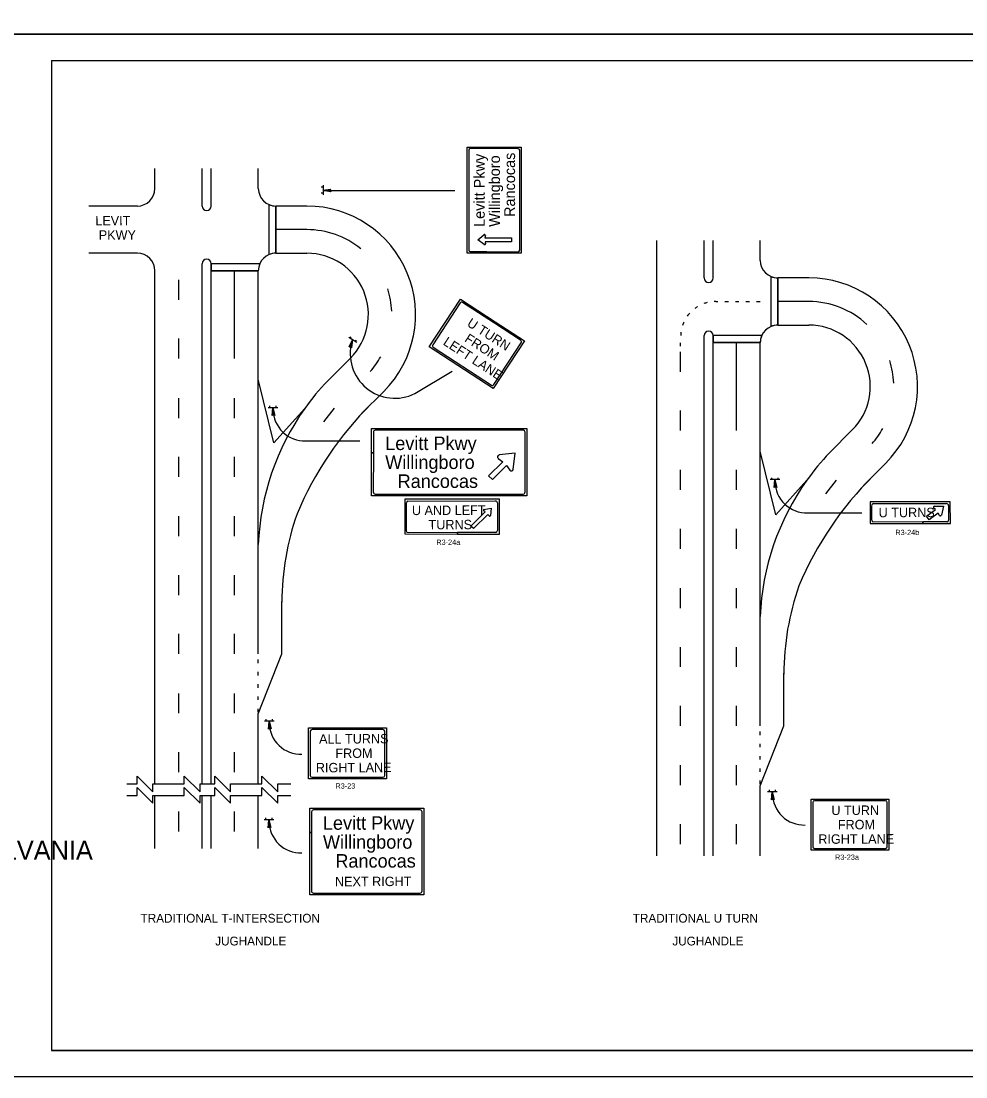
# Model space of a CAD drawing. Extents: x 644898 to 648326, y 298294 to 300670.
# Drawn here: x 647444 to 647982, y 298888 to 299490 of the extents above; entities that cross this region are included whole.
import ezdxf

# ---------------------------------------------------------------- set-up
doc = ezdxf.new("R2010")
doc.units = 0
for name, color, linetype in [('1', 7, 'Continuous'), ('2', 7, 'Continuous'), ('XCS-GRID-MIN', 7, 'Continuous')]:
    doc.layers.add(name, color=color, linetype=linetype)

msp = doc.modelspace()

# ---------------------------------------------------------------- linework, layer by layer
at = {"layer": '1'}
for p, q in [((647461.32, 299467.49), (648247.32, 299467.49)), ((647461.32, 299467.49), (647461.32, 298903.49)), ((648247.32, 298903.49), (647461.32, 298903.49)), ((647461.32, 298903.49), (648047.32, 298903.49))]:
    msp.add_line(p, q, dxfattribs=at)
at = {"layer": '2'}
for p, q in [((647698.12, 299357.77), (647698.12, 299418.14)), ((647698.12, 299418.14), (647728.92, 299418.14)), ((647699, 299416.54), (647699, 299359.53)), ((647727.12, 299417.32), (647699.78, 299417.34)), ((647728.04, 299359.53), (647728.04, 299416.49)), ((647728.92, 299418.14), (647728.92, 299357.77)), ((647520.31, 299394.64), (647520.31, 299406.06)), ((647547.19, 299384.64), (647547.19, 299406.06)), ((647552.28, 299384.64), (647552.28, 299406.06)), ((647579.16, 299394.64), (647579.16, 299406.06)), ((647616, 299395.44), (647614.87, 299395.44)), ((647616, 299391.94), (647614.87, 299391.94)), ((647616, 299396.44), (647616, 299390.94)), ((647616, 299393.57), (647691.11, 299393.57)), ((647510.31, 299384.64), (647482.57, 299384.64)), ((647585.16, 299385.48), (647585.16, 299356.94)), ((647589.16, 299384.65), (647589.16, 299357.77)), ((647606.83, 299384.64), (647589.16, 299384.64)), ((647606.83, 299371.2), (647589.16, 299371.2)), ((647704.1, 299365.4), (647707.54, 299368.27)), ((647708.46, 299367.81), (647708.25, 299366.6)), ((647708.25, 299366.6), (647723.35, 299366.6)), ((647723.35, 299366.6), (647723.35, 299364.34)), ((647707.76, 299362.66), (647704.1, 299365.4)), ((647723.35, 299364.34), (647708.34, 299364.34)), ((647708.34, 299364.34), (647708.53, 299363.19)), ((647806.19, 299014.4), (647806.19, 299365.09)), ((647833.06, 299343.67), (647833.06, 299365.09)), ((647838.15, 299343.67), (647838.15, 299365.09)), ((647865.03, 299353.67), (647865.03, 299365.09)), ((647510.31, 299357.77), (647482.57, 299357.77)), ((647589.16, 299357.77), (647606.83, 299357.77)), ((647709.21, 299357.82), (647698.12, 299357.77)), ((647709.21, 299358.65), (647709.21, 299357.82)), ((647709.21, 299357.82), (647709.21, 299358.65)), ((647728.92, 299357.77), (647709.21, 299357.82)), ((647547.19, 299174.37), (647547.19, 299351.77)), ((647552.28, 299174.37), (647552.28, 299351.77)), ((647579.99, 299351.77), (647552.28, 299351.77)), ((647520.31, 299174.37), (647520.31, 299347.77)), ((647533.81, 299331.24), (647533.81, 299342.62)), ((647579.16, 299347.77), (647552.28, 299347.77)), ((647565.66, 299297.74), (647565.66, 299347.77)), ((647579.16, 299285.94), (647579.16, 299347.77)), ((647871.03, 299344.51), (647871.03, 299315.97)), ((647875.03, 299343.68), (647875.03, 299316.8)), ((647892.7, 299343.67), (647875.03, 299343.67)), ((647676.55, 299304.43), (647694.31, 299331.65)), ((647694.31, 299331.65), (647714.13, 299318.72)), ((647694.05, 299329.43), (647678.48, 299305.56)), ((647713.59, 299317.89), (647695.44, 299329.72)), ((647839.69, 299330.24), (647840.83, 299330.24)), ((647844.82, 299330.24), (647846.84, 299330.24)), ((647850.83, 299330.24), (647852.87, 299330.24)), ((647856.84, 299330.24), (647858.88, 299330.24)), ((647862.85, 299330.24), (647864.89, 299330.24)), ((647892.7, 299330.24), (647875.03, 299330.24)), ((647713.59, 299317.89), (647714.13, 299318.72)), ((647714.13, 299318.72), (647713.59, 299317.89)), ((647714.13, 299318.72), (647730.76, 299307.88)), ((647728.54, 299308.14), (647713.59, 299317.89)), ((647875.03, 299316.8), (647892.7, 299316.8)), ((647533.81, 299297.74), (647533.81, 299309.12)), ((647635.24, 299306.8), (647630.63, 299309.81)), ((647631.47, 299309.26), (647632.09, 299310.21)), ((647634.4, 299307.35), (647635.02, 299308.29)), ((647730.76, 299307.88), (647713, 299280.66)), ((647713.26, 299282.88), (647728.83, 299306.75)), ((647819.69, 299304.8), (647819.69, 299306.78)), ((647833.06, 299014.4), (647833.06, 299310.8)), ((647838.15, 299014.4), (647838.15, 299310.8)), ((647865.86, 299310.8), (647838.15, 299310.8)), ((647865.03, 299306.8), (647838.15, 299306.8)), ((647851.53, 299256.77), (647851.53, 299306.8)), ((647865.03, 299244.97), (647865.03, 299306.8)), ((647713, 299280.66), (647676.55, 299304.43)), ((647678.77, 299304.18), (647711.88, 299282.59)), ((647819.69, 299290.27), (647819.69, 299301.65)), ((647618.5, 299284.95), (647631.58, 299298.02)), ((647668.35, 299277.79), (647689.58, 299290.51)), ((647579.16, 299174.37), (647579.16, 299285.94)), ((647637.97, 299266.42), (647650.57, 299279.03)), ((647533.81, 299263.87), (647533.81, 299275.24)), ((647565.66, 299263.87), (647565.66, 299275.24)), ((647585.8, 299269.71), (647585.8, 299270.84)), ((647589.3, 299269.71), (647589.3, 299270.84)), ((647590.3, 299269.71), (647584.8, 299269.71)), ((647616.48, 299261.61), (647622.59, 299269.47)), ((647819.69, 299256.77), (647819.69, 299268.15)), ((647643.58, 299244.11), (647643.58, 299257.98)), ((647643.58, 299257.98), (647732.13, 299257.98)), ((647730.13, 299256.88), (647645.78, 299256.88)), ((647731.1, 299221.72), (647731.12, 299255.9)), ((647732.13, 299257.98), (647732.13, 299219.47)), ((647904.38, 299243.98), (647917.45, 299257.06)), ((647606.18, 299250.84), (647637.05, 299250.84)), ((647533.81, 299230.37), (647533.81, 299241.74)), ((647565.66, 299230.37), (647565.66, 299241.74)), ((647644.68, 299244.11), (647643.58, 299244.11)), ((647643.58, 299219.47), (647643.58, 299244.11)), ((647643.58, 299244.11), (647644.68, 299244.11)), ((647715.8, 299240.74), (647718.41, 299238.96)), ((647725.43, 299243.91), (647716.35, 299242.81)), ((647724.33, 299234.56), (647725.43, 299243.91)), ((647865.03, 299133.4), (647865.03, 299244.97)), ((647718.41, 299238.96), (647710.3, 299230.98)), ((647712.5, 299228.78), (647720.48, 299236.76)), ((647720.48, 299236.76), (647722.4, 299234.14)), ((647819.69, 299222.9), (647819.69, 299234.27)), ((647851.53, 299222.9), (647851.53, 299234.27)), ((647923.84, 299225.45), (647936.45, 299238.06)), ((647710.3, 299230.98), (647712.5, 299228.78)), ((647876.18, 299228.75), (647870.68, 299228.75)), ((647871.68, 299228.75), (647871.68, 299229.87)), ((647875.18, 299228.75), (647875.18, 299229.87)), ((647902.35, 299220.64), (647908.47, 299228.5)), ((647732.13, 299219.47), (647643.58, 299219.47)), ((647645.78, 299220.57), (647730.07, 299220.57)), ((647716.43, 299217.58), (647662.52, 299217.58)), ((647662.52, 299217.58), (647662.58, 299197.81)), ((647664.39, 299216.54), (647714.07, 299216.61)), ((647716.43, 299197.74), (647716.43, 299217.58)), ((647663.49, 299199.62), (647663.46, 299215.53)), ((647700.2, 299202.29), (647708.38, 299210.38)), ((647708.38, 299210.38), (647707.52, 299210.99)), ((647707.68, 299211.83), (647711.79, 299212.43)), ((647711.79, 299212.43), (647711.43, 299208.37)), ((647715.32, 299215.58), (647715.32, 299199.76)), ((647973.17, 299216.14), (647927.59, 299216.14)), ((647927.59, 299216.14), (647927.65, 299203.75)), ((647928.56, 299205.63), (647928.53, 299214.09)), ((647929.46, 299215.1), (647970.95, 299215.18)), ((647959.71, 299207.94), (647964.76, 299211.66)), ((647964.76, 299211.66), (647963.8, 299212.57)), ((647964.15, 299213.57), (647969.34, 299213.57)), ((647969.34, 299213.57), (647968.16, 299208.61)), ((647972.21, 299214.1), (647972.18, 299205.79)), ((647973.31, 299203.75), (647973.17, 299216.14)), ((647533.81, 299196.49), (647533.81, 299207.87)), ((647565.66, 299196.49), (647565.66, 299207.87)), ((647709.9, 299208.99), (647701.65, 299200.83)), ((647710.54, 299208.07), (647709.9, 299208.99)), ((647892.05, 299209.87), (647922.92, 299209.87)), ((647957.61, 299204.69), (647929.54, 299204.6)), ((647971.63, 299204.76), (647957.61, 299204.69)), ((647957.63, 299203.8), (647957.61, 299204.69)), ((647957.61, 299204.69), (647957.63, 299203.8)), ((647961.22, 299205.88), (647959.71, 299207.94)), ((647966.38, 299209.66), (647961.22, 299205.88)), ((647967.01, 299208.41), (647966.38, 299209.66)), ((647692.54, 299198.68), (647664.52, 299198.54)), ((647714.36, 299198.71), (647692.54, 299198.68)), ((647692.56, 299197.78), (647692.54, 299198.68)), ((647692.54, 299198.68), (647692.56, 299197.78)), ((647701.65, 299200.83), (647700.2, 299202.29)), ((647819.69, 299189.4), (647819.69, 299200.77)), ((647851.53, 299189.4), (647851.53, 299200.77)), ((647927.65, 299203.75), (647957.63, 299203.8)), ((647957.63, 299203.8), (647973.31, 299203.75)), ((647662.58, 299197.81), (647692.56, 299197.78)), ((647692.56, 299197.78), (647716.43, 299197.74)), ((647520.31, 299055.37), (647520.31, 299174.37)), ((647533.81, 299162.99), (647533.81, 299174.37)), ((647547.19, 299055.37), (647547.19, 299174.37)), ((647552.28, 299055.37), (647552.28, 299174.37)), ((647565.66, 299162.99), (647565.66, 299174.37)), ((647579.16, 299129.49), (647579.16, 299174.37)), ((647819.69, 299155.52), (647819.69, 299166.9)), ((647851.53, 299155.52), (647851.53, 299166.9)), ((647592.61, 299129.49), (647592.61, 299159.42)), ((647533.81, 299129.49), (647533.81, 299140.87)), ((647565.66, 299129.49), (647565.66, 299140.87)), ((647819.69, 299122.02), (647819.69, 299133.4)), ((647851.53, 299122.02), (647851.53, 299133.4)), ((647865.03, 299088.52), (647865.03, 299133.4)), ((647579.16, 299095.24), (647592.61, 299129.49)), ((647579.16, 299124.24), (647579.16, 299126.24)), ((647579.16, 299117.24), (647579.16, 299119.24)), ((647878.49, 299088.52), (647878.49, 299118.45)), ((647579.16, 299110.24), (647579.16, 299112.24)), ((647533.81, 299095.62), (647533.81, 299106.99)), ((647565.66, 299095.62), (647565.66, 299106.99)), ((647579.16, 299103.24), (647579.16, 299105.24)), ((647579.16, 299096.24), (647579.16, 299098.24)), ((647819.69, 299088.52), (647819.69, 299099.9)), ((647851.53, 299088.52), (647851.53, 299099.9)), ((647579.16, 299055.37), (647579.16, 299095.24)), ((647588.16, 299091.15), (647582.66, 299091.15)), ((647583.66, 299091.15), (647583.66, 299092.27)), ((647587.16, 299091.15), (647587.16, 299092.27)), ((647607.74, 299058.23), (647607.74, 299087.4)), ((647607.74, 299087.4), (647629.04, 299087.39)), ((647608.74, 299085.4), (647608.74, 299060.23)), ((647629.02, 299086.4), (647609.74, 299086.4)), ((647629.02, 299086.4), (647629.04, 299087.4)), ((647629.04, 299087.39), (647629.02, 299086.4)), ((647650.13, 299086.4), (647629.02, 299086.4)), ((647629.04, 299087.4), (647652.13, 299087.4)), ((647651.13, 299060.23), (647651.13, 299085.4)), ((647652.13, 299087.4), (647652.13, 299058.23)), ((647865.03, 299054.27), (647878.49, 299088.52)), ((647865.03, 299083.27), (647865.03, 299085.27)), ((647865.03, 299076.27), (647865.03, 299078.27)), ((647533.81, 299062.12), (647533.81, 299073.49)), ((647565.66, 299062.12), (647565.66, 299073.49)), ((647819.69, 299054.65), (647819.69, 299066.02)), ((647851.53, 299054.65), (647851.53, 299066.02)), ((647865.03, 299069.27), (647865.03, 299071.27)), ((647865.03, 299062.27), (647865.03, 299064.27)), ((647504.23, 299055.37), (647510.11, 299055.37)), ((647519.11, 299055.37), (647536.98, 299055.37)), ((647545.98, 299055.37), (647553.48, 299055.37)), ((647548.44, 299055.37), (647554.31, 299055.37)), ((647563.31, 299055.37), (647581.19, 299055.37)), ((647590.19, 299055.37), (647597.69, 299055.37)), ((647652.13, 299058.23), (647607.74, 299058.23)), ((647609.74, 299059.23), (647650.13, 299059.23)), ((647865.03, 299055.27), (647865.03, 299057.27)), ((647865.03, 299014.4), (647865.03, 299054.27)), ((647504.23, 299048.87), (647510.11, 299048.87)), ((647519.11, 299048.87), (647536.98, 299048.87)), ((647520.31, 299018.69), (647520.31, 299048.87)), ((647545.98, 299048.87), (647553.48, 299048.87)), ((647547.19, 299018.69), (647547.19, 299048.87)), ((647548.44, 299048.87), (647554.31, 299048.87)), ((647552.28, 299018.69), (647552.28, 299048.87)), ((647563.31, 299048.87), (647581.19, 299048.87)), ((647579.16, 299018.69), (647579.16, 299048.87)), ((647590.19, 299048.87), (647597.69, 299048.87)), ((647874.71, 299050.86), (647869.21, 299050.86)), ((647870.21, 299050.86), (647870.21, 299051.98)), ((647873.71, 299050.86), (647873.71, 299051.98)), ((647893.93, 299017.63), (647893.93, 299046.79)), ((647893.93, 299046.79), (647915.22, 299046.78)), ((647894.93, 299044.79), (647894.93, 299019.63)), ((647915.21, 299045.79), (647895.93, 299045.79)), ((647915.21, 299045.79), (647915.22, 299046.79)), ((647915.22, 299046.78), (647915.21, 299045.79)), ((647936.32, 299045.79), (647915.21, 299045.79)), ((647915.22, 299046.79), (647938.32, 299046.79)), ((647937.32, 299019.63), (647937.32, 299044.79)), ((647938.32, 299046.79), (647938.32, 299017.63)), ((647533.81, 299028.24), (647533.81, 299039.62)), ((647565.66, 299028.24), (647565.66, 299039.62)), ((647583.52, 299034.96), (647583.52, 299036.08)), ((647587.02, 299034.96), (647587.02, 299036.08)), ((647608.41, 299027.79), (647608.41, 299041.66)), ((647608.41, 299041.66), (647673.41, 299041.66)), ((647671.42, 299040.56), (647610.61, 299040.56)), ((647672.39, 298994.4), (647672.41, 299039.58)), ((647673.41, 299041.66), (647673.41, 298992.15)), ((647588.02, 299034.96), (647582.52, 299034.96)), ((647819.69, 299021.15), (647819.69, 299032.52)), ((647851.53, 299021.15), (647851.53, 299032.52)), ((647609.51, 299027.79), (647608.41, 299027.79)), ((647608.41, 298992.15), (647608.41, 299027.79)), ((647608.41, 299027.79), (647609.51, 299027.79)), ((647895.93, 299018.63), (647936.32, 299018.63)), ((647938.32, 299017.63), (647893.93, 299017.63)), ((647673.41, 298992.15), (647608.41, 298992.15)), ((647610.61, 298993.25), (647671.36, 298993.25))]:
    msp.add_line(p, q, dxfattribs=at)
for points in [[(647620.22, 299393.09), (647620.12, 299393.35), (647616, 299393.57), (647620.22, 299393.09), (647620.45, 299392.82), (647616, 299393.57), (647620.16, 299393.85), (647620.3, 299394.08), (647616, 299393.57), (647620.45, 299394.32), (647620.3, 299394.08)], [(647585.16, 299385.47), (647585.16, 299356.94)], [(647589.16, 299357.77), (647589.16, 299371.2), (647589.16, 299384.64)], [(647699.88, 299358.65), (647709.21, 299358.65)], [(647709.21, 299358.65), (647727.12, 299358.59)], [(647579.99, 299351.77), (647552.28, 299351.77), (647552.28, 299347.77), (647565.66, 299347.77), (647579.16, 299347.77)], [(647871.03, 299344.5), (647871.03, 299315.97)], [(647875.03, 299316.8), (647875.03, 299330.24), (647875.03, 299343.67)], [(647631.16, 299304.47), (647631.43, 299304.49), (647632.83, 299308.38), (647631.16, 299304.47), (647630.83, 299304.33), (647632.83, 299308.38), (647631.9, 299304.31), (647632.09, 299304.1), (647632.83, 299308.38), (647632.27, 299303.89), (647632.09, 299304.1)], [(647865.86, 299310.8), (647838.15, 299310.8), (647838.15, 299306.8), (647851.53, 299306.8), (647865.03, 299306.8)], [(647605.63, 299269.35), (647587.95, 299249.74), (647579.16, 299285.94)], [(647587.3, 299265.46), (647587.55, 299265.59), (647587.43, 299269.71), (647587.3, 299265.46), (647587.05, 299265.21), (647587.43, 299269.71), (647588.05, 299265.59), (647588.3, 299265.46), (647587.43, 299269.71), (647588.55, 299265.34), (647588.3, 299265.46)], [(647644.68, 299255.78), (647644.68, 299244.11)], [(647644.68, 299244.11), (647644.61, 299221.72)], [(647891.5, 299228.38), (647873.83, 299208.78), (647865.03, 299244.97)], [(647873.18, 299224.5), (647873.43, 299224.62), (647873.3, 299228.75), (647873.18, 299224.5), (647872.93, 299224.25), (647873.3, 299228.75), (647873.93, 299224.62), (647874.18, 299224.5), (647873.3, 299228.75), (647874.43, 299224.37), (647874.18, 299224.5)], [(647585.16, 299086.9), (647585.41, 299087.02), (647585.28, 299091.15), (647585.16, 299086.9), (647584.91, 299086.65), (647585.28, 299091.15), (647585.91, 299087.02), (647586.16, 299086.9), (647585.28, 299091.15), (647586.41, 299086.77), (647586.16, 299086.9)], [(647510.11, 299055.37), (647510.11, 299059.87), (647519.11, 299050.87), (647519.11, 299055.37)], [(647536.98, 299055.37), (647536.98, 299059.87), (647545.98, 299050.87), (647545.98, 299055.37)], [(647554.31, 299055.37), (647554.31, 299059.87), (647563.31, 299050.87), (647563.31, 299055.37)], [(647581.19, 299055.37), (647581.19, 299059.87), (647590.19, 299050.87), (647590.19, 299055.37)], [(647510.11, 299048.87), (647510.11, 299053.37), (647519.11, 299044.37), (647519.11, 299048.87)], [(647536.98, 299048.87), (647536.98, 299053.37), (647545.98, 299044.37), (647545.98, 299048.87)], [(647554.31, 299048.87), (647554.31, 299053.37), (647563.31, 299044.37), (647563.31, 299048.87)], [(647581.19, 299048.87), (647581.19, 299053.37), (647590.19, 299044.37), (647590.19, 299048.87)], [(647871.71, 299046.61), (647871.96, 299046.73), (647871.83, 299050.86), (647871.71, 299046.61), (647871.46, 299046.36), (647871.83, 299050.86), (647872.46, 299046.73), (647872.71, 299046.61), (647871.83, 299050.86), (647872.96, 299046.48), (647872.71, 299046.61)], [(647609.51, 299039.46), (647609.51, 299027.79)], [(647585.02, 299030.71), (647585.27, 299030.83), (647585.15, 299034.96), (647585.02, 299030.71), (647584.77, 299030.46), (647585.15, 299034.96), (647585.77, 299030.83), (647586.02, 299030.71), (647585.15, 299034.96), (647586.27, 299030.58), (647586.02, 299030.71)], [(647609.51, 299027.79), (647609.44, 298994.4)]]:
    msp.add_lwpolyline(points, dxfattribs=at)
for centre, radius, start, end in [((647510.31, 299394.64), 10, 270, 0), ((647589.16, 299394.64), 10, 180, 270), ((647549.73, 299384.64), 2.55, 180, 360), ((647589.16, 299394.64), 10, 246.42182, 270), ((647606.83, 299322.77), 61.87, 315.00253, 90), ((647606.83, 299322.77), 48.43, 50.74117, 90), ((647707.92, 299367.88), 0.524, 350.16586, 134.07249), ((647708, 299363.16), 0.524, 232.49416, 10.0182), ((647510.31, 299347.77), 10, 0, 90), ((647589.16, 299347.77), 10, 90, 180), ((647589.16, 299347.77), 10, 90, 113.57818), ((647606.83, 299322.77), 35, 315.00253, 90), ((647549.73, 299351.77), 2.55, 0, 180), ((647589.16, 299347.77), 10, 156.42182, 180), ((647875.03, 299353.67), 10, 180, 270), ((647835.61, 299343.67), 2.55, 180, 360), ((647875.03, 299353.67), 10, 246.42182, 270), ((647892.7, 299281.8), 61.87, 315.00253, 90), ((647596.46, 299320.95), 58.87, 3.73635, 16.39001), ((647694.89, 299328.89), 1, 56.88866, 146.88866), ((647839.69, 299310.24), 20, 121.11269, 126.8023), ((647839.69, 299310.24), 20, 104.01816, 109.65455), ((647839.69, 299310.24), 20, 90, 92.51007), ((647892.7, 299281.8), 48.43, 46.92144, 90), ((647839.69, 299310.24), 20, 155.44231, 161.30759), ((647839.69, 299310.24), 20, 138.12039, 144.15375), ((647839.69, 299310.24), 20, 172.58031, 178.41631), ((647835.61, 299310.8), 2.55, 0, 180), ((647875.03, 299306.8), 10, 90, 180), ((647875.03, 299306.8), 10, 90, 113.57818), ((647892.7, 299281.8), 35, 315.00253, 90), ((647656.99, 299300.65), 25.53, 164.51358, 296.41842), ((647875.03, 299306.8), 10, 156.42182, 180), ((647679.32, 299305.01), 1, 146.88866, 236.88866), ((647606.08, 299322.53), 48.93, 318.77084, 331.01301), ((647882.34, 299279.98), 58.87, 3.73635, 16.39001), ((647722.19, 299186.27), 143.14, 136.41553, 144.51975), ((647779.78, 299134.31), 193.7, 134.7239, 157.21756), ((647722.19, 299186.27), 143.14, 144.51975, 177.78837), ((647605.56, 299268.83), 18.01, 180.38521, 271.96908), ((647645.78, 299255.78), 1.1, 90, 180), ((647891.95, 299281.56), 48.93, 318.77084, 331.01301), ((647716.46, 299241.7), 1.08, 94.85646, 235.52198), ((648008.06, 299145.3), 143.14, 136.41553, 144.51975), ((647723.31, 299234.77), 1.08, 213.24494, 357.15157), ((648008.06, 299145.3), 143.14, 144.51975, 177.78837), ((648065.65, 299093.34), 193.7, 134.7239, 157.21756), ((647891.43, 299227.87), 18.01, 180.38521, 271.96908), ((647707.85, 299211.36), 0.477, 97.49388, 235.01792), ((647964.27, 299212.96), 0.596, 89.18506, 226.70909), ((647743.46, 299159.16), 150.85, 160.58015, 180.10119), ((647710.93, 299208.38), 0.477, 215.16557, 359.07221), ((647929.5, 299205.65), 1, 181.51424, 269.92714), ((647967.54, 299208.71), 0.596, 206.85675, 350.76338), ((648029.34, 299118.19), 150.85, 160.58015, 180.10119), ((647603.41, 299090.27), 18.01, 180.38521, 271.96908), ((647650.13, 299085.4), 1, 0, 90), ((647889.96, 299049.98), 18.01, 180.38521, 271.96908), ((647936.32, 299044.79), 1, 0, 90), ((647610.61, 299039.46), 1.1, 90, 180), ((647603.28, 299034.08), 18.01, 180.38521, 271.96908)]:
    msp.add_arc(centre, radius, start, end, dxfattribs=at)
for centre, major_axis, ratio, start_param, end_param in [((647699.78, 299416.54), (0, -0.794), 0.982768, 3.141593, 4.712389), ((647727.12, 299416.49), (0.921, 0), 0.891691, 0, 1.570796), ((647699.88, 299359.53), (0, -0.88), 0.999828, 4.712389, 6.283185), ((647727.12, 299359.53), (0, -0.937), 0.982744, 0, 1.570796), ((647727.99, 299307.3), (-0.838, 0.546), 0.99966, 3.141593, 4.712389), ((647712.42, 299283.43), (-0.546, -0.838), 0.999893, 0, 1.570796), ((647730.13, 299255.9), (-0.992, 0), 0.982768, 3.141593, 4.712389), ((647645.78, 299221.72), (-1.17, 0), 0.982767, 0, 1.570796), ((647664.39, 299215.53), (0, 1.03), 0.878961, 6.274622, 7.830789), ((647714.06, 299215.58), (1.27, 0), 0.785349, 6.244238, 7.846016), ((647730.07, 299221.72), (0, -1.15), 0.891691, 0, 1.570796), ((647929.46, 299214.1), (0, 1.03), 0.878961, 6.274622, 7.830789), ((647970.94, 299214.09), (1.28, 0), 0.813513, 6.244238, 7.846016), ((647971.57, 299205.74), (0, 1.02), 0.621379, 3.154879, 4.734147), ((647664.48, 299199.64), (0, -1.05), 0.995861, 4.738818, 6.281914), ((647714.29, 299199.71), (1.06, 0), 0.98528, 4.725675, 6.304944), ((647609.74, 299085.4), (0, 1), 0.999929, 0, 1.570796), ((647609.74, 299060.23), (0, -1), 0.999785, 4.712389, 6.283185), ((647650.13, 299060.23), (0, -1), 0.998065, 0, 1.570796), ((647895.93, 299044.79), (0, 1), 0.999929, 0, 1.570796), ((647671.42, 299039.58), (-0.992, 0), 0.982644, 3.141593, 4.712389), ((647895.93, 299019.63), (0, -1), 0.999785, 4.712389, 6.283185), ((647936.32, 299019.63), (0, -1), 0.998065, 0, 1.570796), ((647610.61, 298994.4), (-1.17, 0), 0.982757, 0, 1.570796), ((647671.36, 298994.4), (0, -1.15), 0.8915, 0, 1.570796)]:
    msp.add_ellipse(centre, major_axis=major_axis, ratio=ratio, start_param=start_param, end_param=end_param, dxfattribs=at)
at = {"layer": 'XCS-GRID-MIN'}
for points in [[(647421.32, 300076.49), (648262.32, 300076.49), (648262.32, 299482.49), (647421.32, 299482.49)], [(647421.32, 299482.49), (648262.32, 299482.49), (648262.32, 298888.49), (647421.32, 298888.49)]]:
    msp.add_lwpolyline(points, close=True, dxfattribs=at)

# ---------------------------------------------------------------- texts
at = {"layer": '1'}
msp.add_text('COMMONWEALTH OF PENNSYLVANIA', height=10.7828, dxfattribs=at).set_placement((647218.92, 299012.23))
at = {"layer": '2'}
for s, height, rotation, p in [('Rancocas', 6.16, 89.99976, (647725.38, 299378.42)), ('Levitt Pkwy', 6.1598, 89.99976, (647708.11, 299372.75)), ('Willingboro', 6.1598, 89.99976, (647716.74, 299372.77)), ('LEVIT', 5.375, 0.20237, (647486.32, 299373.6)), ('PKWY', 5.375, 0.20237, (647488.29, 299365.42)), ('U TURN', 5.375, 327.09102, (647697.58, 299316.64)), ('LEFT LANE', 5.375, 327.09102, (647683.97, 299305.94)), ('FROM', 5.375, 327.09102, (647696.2, 299307.78)), ('Levitt Pkwy', 7.6997, 359.99976, (647651.42, 299245.62)), ('Willingboro', 7.6997, 359.99976, (647651.44, 299234.83)), ('Rancocas', 7.7, 359.99976, (647658.5, 299224.03)), ('U AND LEFT', 5.375, 0.20237, (647666.63, 299208.57)), ('U TURNS', 5.375, 0.20237, (647932.44, 299207.32)), ('TURNS', 5.375, 0.20237, (647676.12, 299200.41)), ('ALL TURNS', 5.375, 0.20237, (647613.76, 299078.35)), ('FROM', 5.375, 0.20237, (647623.06, 299070.19)), ('RIGHT LANE', 5.375, 0.20237, (647611.94, 299061.96)), ('U TURN', 5.375, 0.20237, (647905.53, 299037.68)), ('Levitt Pkwy', 7.6997, 359.99976, (647615.95, 299029.3)), ('FROM', 5.375, 0.20237, (647909.22, 299029.51)), ('Willingboro', 7.6997, 359.99976, (647615.97, 299018.5)), ('RIGHT LANE', 5.375, 0.20237, (647898.1, 299021.28)), ('Rancocas', 7.7, 359.99976, (647623.04, 299007.71)), ('NEXT RIGHT', 5.375, 0.20237, (647622.81, 298997.08))]:
    msp.add_text(s, height=height, rotation=rotation, dxfattribs=at).set_placement(p)
for s, height, p in [('R3-24b', 3, (647941.97, 299197.17)), ('R3-24a', 3, (647680.55, 299191.6)), ('R3-23', 3, (647623.09, 299052.74)), ('R3-23a', 3, (647907.63, 299012.16)), ('TRADITIONAL T-INTERSECTION', 5, (647512.08, 298976.38)), ('TRADITIONAL U TURN', 5, (647792.42, 298976.38)), ('JUGHANDLE', 5, (647554.6, 298963.38)), ('JUGHANDLE', 5, (647814.94, 298963.38))]:
    msp.add_text(s, height=height, dxfattribs=at).set_placement(p)

doc.saveas('drawing.dxf')
